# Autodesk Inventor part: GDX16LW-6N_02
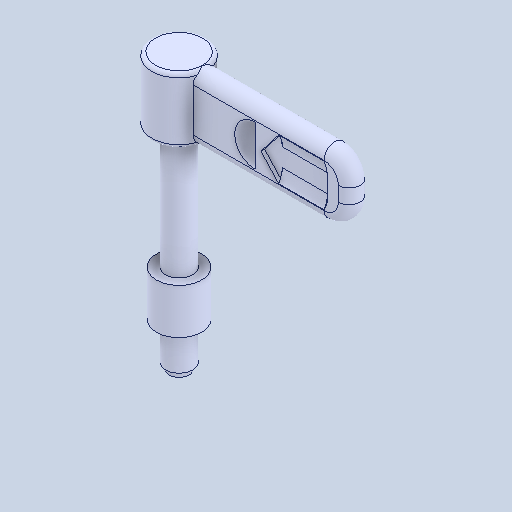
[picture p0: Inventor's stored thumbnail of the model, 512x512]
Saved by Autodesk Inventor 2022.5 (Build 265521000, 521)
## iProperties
Created: 2024-06
Part Number: GDX16LW-6N_02
Material: 一般
Document SubType Name: Modeling
Designer: ImaoCorp
Density: 1 g/cm^3
Appearance: 既定
Author: ImaoCorp
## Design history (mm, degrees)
feature "GDX16LW-6N_02"
node "ソリッド1"
